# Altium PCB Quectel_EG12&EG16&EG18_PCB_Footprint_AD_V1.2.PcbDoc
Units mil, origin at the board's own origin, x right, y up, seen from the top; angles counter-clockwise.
Board outline 6000 x 4000 mil, 2 copper layers (Top Layer, Bottom Layer); 1 components, 0 nets, 299 pads, 0 vias.
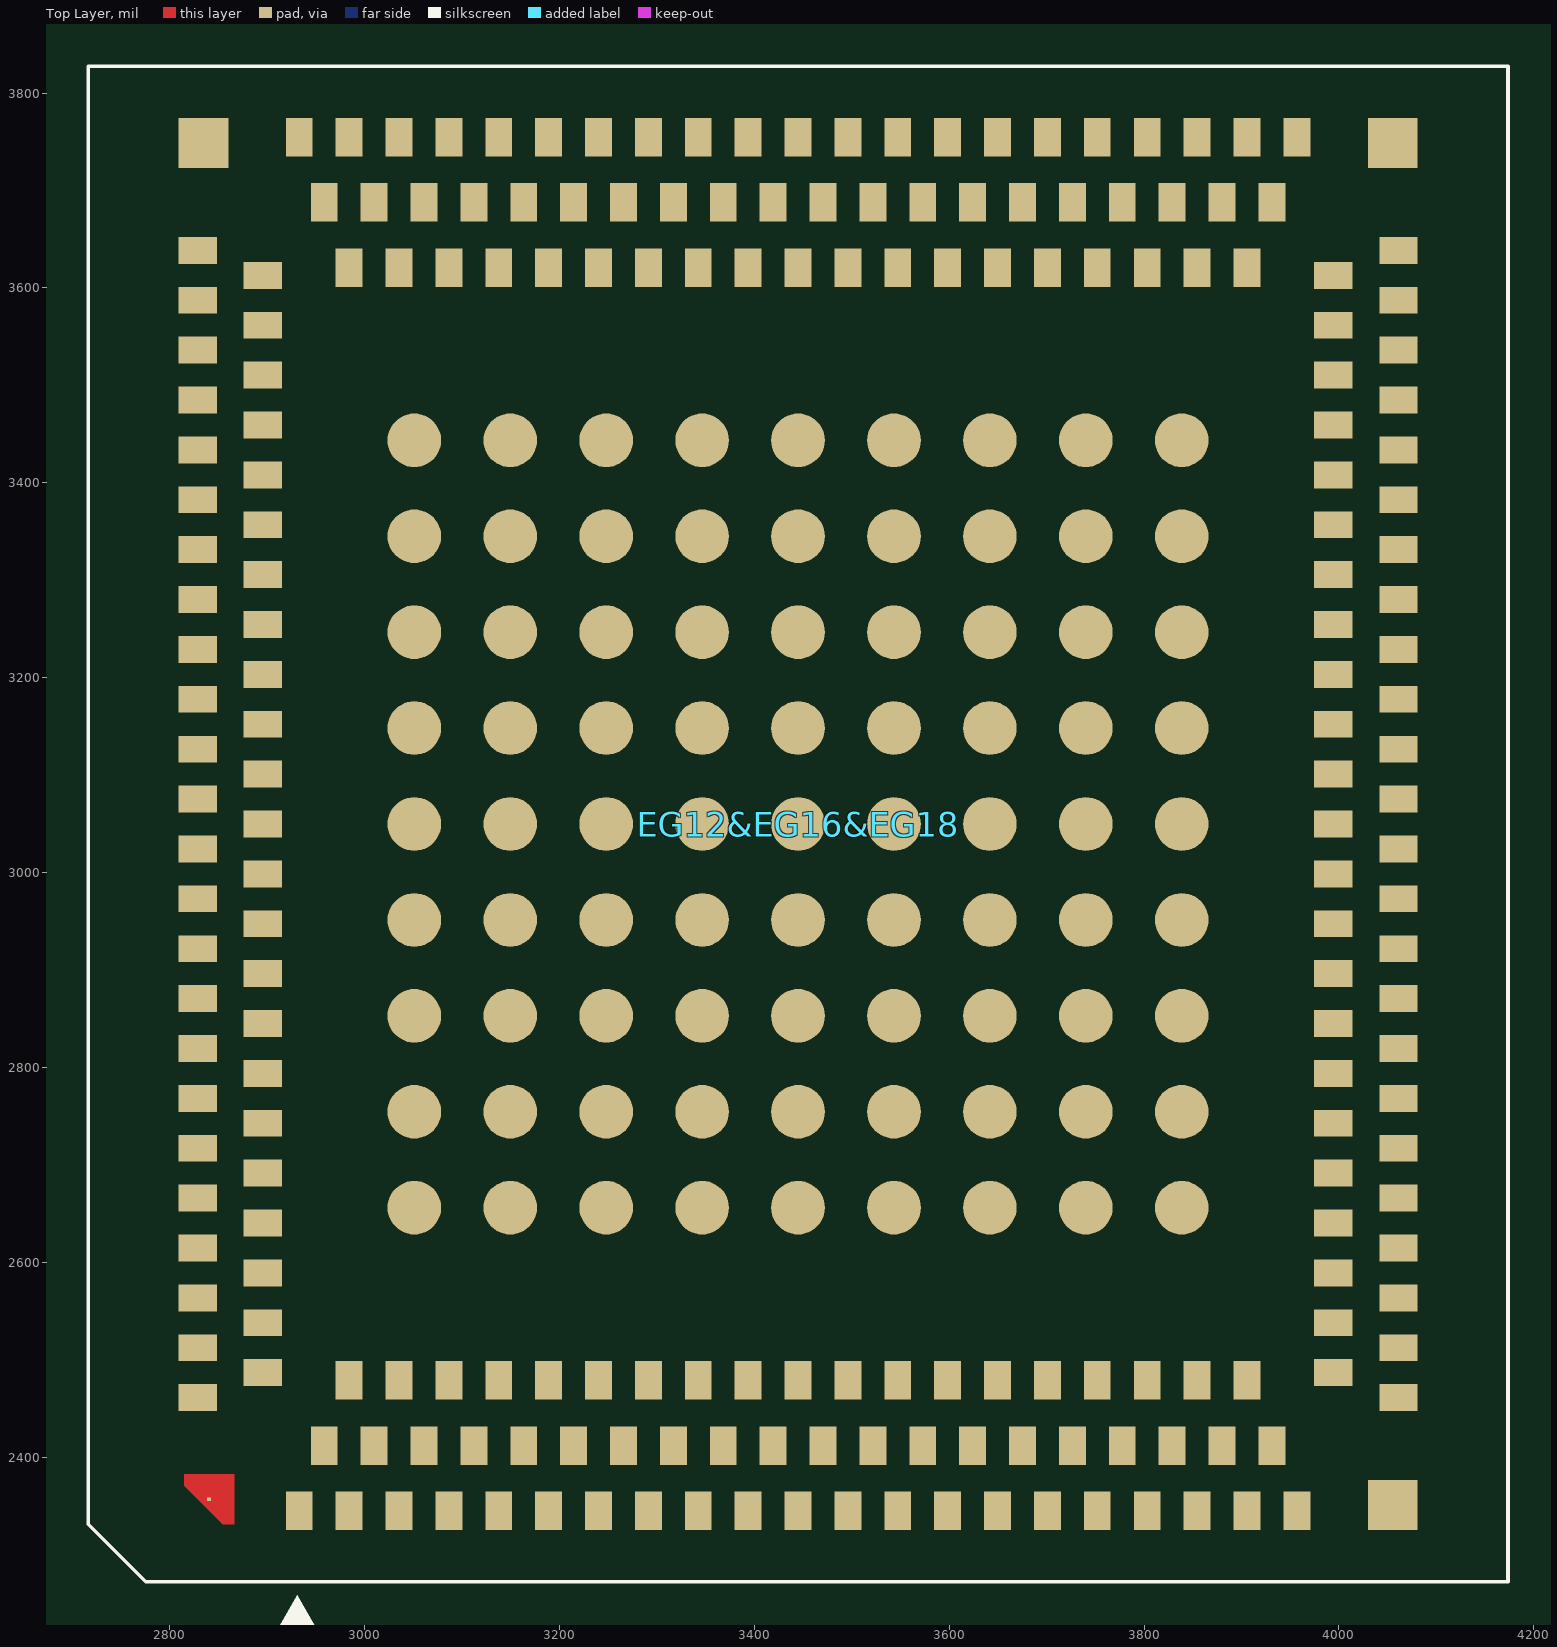
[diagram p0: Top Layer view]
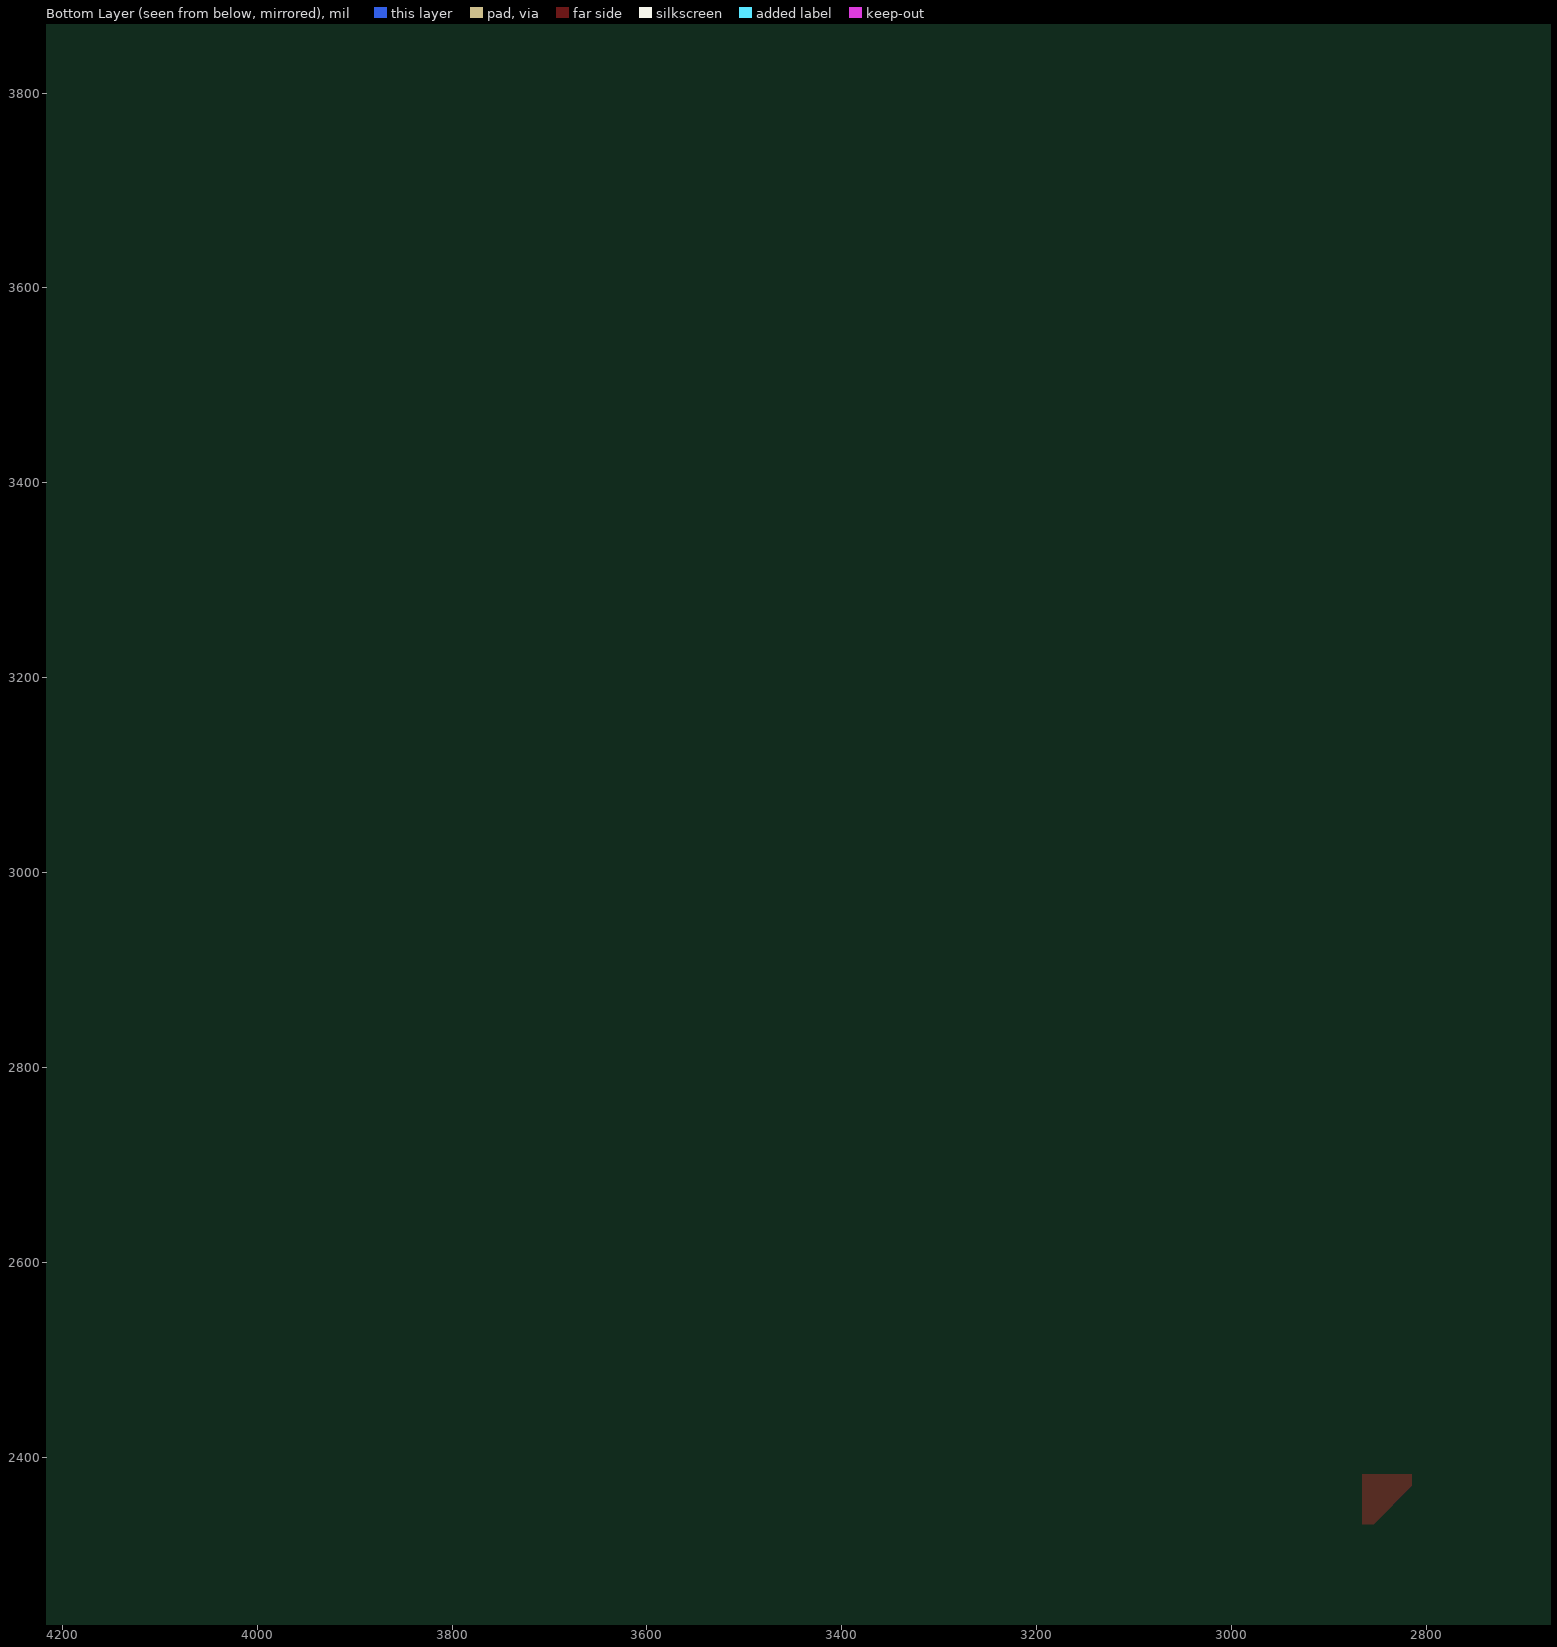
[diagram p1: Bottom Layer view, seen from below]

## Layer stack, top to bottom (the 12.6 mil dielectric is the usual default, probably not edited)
Top Layer: signal copper 1.4
Dielectric: dielectric 12.6, FR-4, Dk 4.8
Bottom Layer: signal copper 1.4

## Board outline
1000,1000 7000,1000 7000,5000 1000,5000

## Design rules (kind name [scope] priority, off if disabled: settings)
Clearance [All] p1: gap=10
PolygonConnect [All] p1: connectstyle=Relief reliefconductorwidth=10 reliefentries=4 polygonreliefangle="90 Angle" airgapwidth=10
RoutingVias [All] p1: holewidth=28 width=50 viastyle="Through Hole" minholewidth=28 minwidth=50 maxholewidth=28 maxwidth=50
SolderMaskExpansion [All] p1: expansion=4
Width [All] p1: maxlimit=10 minlimit=10 preferedwidth=10
28 further rules are at their usual default settings.

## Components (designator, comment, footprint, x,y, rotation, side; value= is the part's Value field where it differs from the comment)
EG12&EG16&EG18 "Comment" EG12&EG16&EG18 3445,3050 r0 top

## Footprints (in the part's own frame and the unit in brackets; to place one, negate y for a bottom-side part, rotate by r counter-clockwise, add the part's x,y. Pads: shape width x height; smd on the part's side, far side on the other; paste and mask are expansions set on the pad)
EG12&EG16&EG18 [mm]
  rect 0.7x1 smd mask+0.05: 1(-13,-17.9) 2(-12.35,-16.2) 3(-11.7,-17.9) 4(-11.05,-16.2) 5(-10.4,-17.9) 6(-9.75,-16.2) 7(-9.1,-17.9) 8(-8.45,-16.2) 9(-7.8,-17.9) 10(-7.15,-16.2) 11(-6.5,-17.9) 12(-5.85,-16.2) 13(-5.2,-17.9) 14(-4.55,-16.2) 15(-3.9,-17.9) 16(-3.25,-16.2) 17(-2.6,-17.9) 18(-1.95,-16.2) 19(-1.3,-17.9) 20(-0.65,-16.2) 21(0,-17.9) 22(0.65,-16.2) 23(1.3,-17.9) 24(1.95,-16.2) 25(2.6,-17.9) 26(3.25,-16.2) 27(3.9,-17.9) 28(4.55,-16.2) 29(5.2,-17.9) 30(5.85,-16.2) 31(6.5,-17.9) 32(7.15,-16.2) 33(7.8,-17.9) 34(8.45,-16.2) 35(9.1,-17.9) 36(9.75,-16.2) 37(10.4,-17.9) 38(11.05,-16.2) 39(11.7,-17.9) 40(12.35,-16.2) 41(13,-17.9) 89(13,17.9) 90(12.35,16.2) 91(11.7,17.9) 92(11.05,16.2) 93(10.4,17.9) 94(9.75,16.2) 95(9.1,17.9) 96(8.45,16.2) 97(7.8,17.9) 98(7.15,16.2) 99(6.5,17.9) 100(5.85,16.2) 101(5.2,17.9) 102(4.55,16.2) 103(3.9,17.9) 104(3.25,16.2) 105(2.6,17.9) 106(1.95,16.2) 107(1.3,17.9) 108(0.65,16.2) 109(0,17.9) 110(-0.65,16.2) 111(-1.3,17.9) 112(-1.95,16.2) 113(-2.6,17.9) 114(-3.25,16.2) 115(-3.9,17.9) 116(-4.55,16.2) 117(-5.2,17.9) 118(-5.85,16.2) 119(-6.5,17.9) 120(-7.15,16.2) 121(-7.8,17.9) 122(-8.45,16.2) 123(-9.1,17.9) 124(-9.75,16.2) 125(-10.4,17.9) 126(-11.05,16.2) 127(-11.7,17.9) 128(-12.35,16.2) 129(-13,17.9) 177(-11.7,-14.5) 178(-10.4,-14.5) 179(-9.1,-14.5) 180(-7.8,-14.5) 181(-6.5,-14.5) 182(-5.2,-14.5) 183(-3.9,-14.5) 184(-2.6,-14.5) 185(-1.3,-14.5) 186(0,-14.5) 187(1.3,-14.5) 188(2.6,-14.5) 189(3.9,-14.5) 190(5.2,-14.5) 191(6.5,-14.5) 192(7.8,-14.5) 193(9.1,-14.5) 194(10.4,-14.5) 195(11.7,-14.5) 196(11.7,14.5) 197(10.4,14.5) 198(9.1,14.5) 199(7.8,14.5) 200(6.5,14.5) 201(5.2,14.5) 202(3.9,14.5) 203(2.6,14.5) 204(1.3,14.5) 205(0,14.5) 206(-1.3,14.5) 207(-2.6,14.5) 208(-3.9,14.5) 209(-5.2,14.5) 210(-6.5,14.5) 211(-7.8,14.5) 212(-9.1,14.5) 213(-10.4,14.5) 214(-11.7,14.5)
  rect 1x0.7 smd mask+0.05: 42(15.65,-14.95) 43(13.95,-14.3) 44(15.65,-13.65) 45(13.95,-13) 46(15.65,-12.35) 47(13.95,-11.7) 48(15.65,-11.05) 49(13.95,-10.4) 50(15.65,-9.75) 51(13.95,-9.1) 52(15.65,-8.45) 53(13.95,-7.8) 54(15.65,-7.15) 55(13.95,-6.5) 56(15.65,-5.85) 57(13.95,-5.2) 58(15.65,-4.55) 59(13.95,-3.9) 60(15.65,-3.25) 61(13.95,-2.6) 62(15.65,-1.95) 63(13.95,-1.3) 64(15.65,-0.65) 65(13.95,0) 66(15.65,0.65) 67(13.95,1.3) 68(15.65,1.95) 69(13.95,2.6) 70(15.65,3.25) 71(13.95,3.9) 72(15.65,4.55) 73(13.95,5.2) 74(15.65,5.85) 75(13.95,6.5) 76(15.65,7.15) 77(13.95,7.8) 78(15.65,8.45) 79(13.95,9.1) 80(15.65,9.75) 81(13.95,10.4) 82(15.65,11.05) 83(13.95,11.7) 84(15.65,12.35) 85(13.95,13) 86(15.65,13.65) 87(13.95,14.3) 88(15.65,14.95) 130(-15.65,14.95) 131(-13.95,14.3) 132(-15.65,13.65) 133(-13.95,13) 134(-15.65,12.35) 135(-13.95,11.7) 136(-15.65,11.05) 137(-13.95,10.4) 138(-15.65,9.75) 139(-13.95,9.1) 140(-15.65,8.45) 141(-13.95,7.8) 142(-15.65,7.15) 143(-13.95,6.5) 144(-15.65,5.85) 145(-13.95,5.2) 146(-15.65,4.55) 147(-13.95,3.9) 148(-15.65,3.25) 149(-13.95,2.6) 150(-15.65,1.95) 151(-13.95,1.3) 152(-15.65,0.65) 153(-13.95,0) 154(-15.65,-0.65) 155(-13.95,-1.3) 156(-15.65,-1.95) 157(-13.95,-2.6) 158(-15.65,-3.25) 159(-13.95,-3.9) 160(-15.65,-4.55) 161(-13.95,-5.2) 162(-15.65,-5.85) 163(-13.95,-6.5) 164(-15.65,-7.15) 165(-13.95,-7.8) 166(-15.65,-8.45) 167(-13.95,-9.1) 168(-15.65,-9.75) 169(-13.95,-10.4) 170(-15.65,-11.05) 171(-13.95,-11.7) 172(-15.65,-12.35) 173(-13.95,-13) 174(-15.65,-13.65) 175(-13.95,-14.3) 176(-15.65,-14.95)
  round 1.4 smd mask+0.05: 215(-10,10) 216(-7.5,10) 217(-5,10) 218(-2.5,10) 219(0,10) 220(2.5,10) 221(5,10) 222(7.5,10) 223(10,10) 224(-10,7.5) 225(-7.5,7.5) 226(-5,7.5) 227(-2.5,7.5) 228(0,7.5) 229(2.5,7.5) 230(5,7.5) 231(7.5,7.5) 232(10,7.5) 233(-10,5) 234(-7.5,5) 235(-5,5) 236(-2.5,5) 237(0,5) 238(2.5,5) 239(5,5) 240(7.5,5) 241(10,5) 242(-10,2.5) 243(-7.5,2.5) 244(-5,2.5) 245(-2.5,2.5) 246(0,2.5) 247(2.5,2.5) 248(5,2.5) 249(7.5,2.5) 250(10,2.5) 251(-10,0) 252(-7.5,0) 253(-5,0) 254(-2.5,0) 255(0,0) 256(2.5,0) 257(5,0) 258(7.5,0) 259(10,0) 260(-10,-2.5) 261(-7.5,-2.5) 262(-5,-2.5) 263(-2.5,-2.5) 264(0,-2.5) 265(2.5,-2.5) 266(5,-2.5) 267(7.5,-2.5) 268(10,-2.5) 269(-10,-5) 270(-7.5,-5) 271(-5,-5) 272(-2.5,-5) 273(0,-5) 274(2.5,-5) 275(5,-5) 276(7.5,-5) 277(10,-5) 278(-10,-7.5) 279(-7.5,-7.5) 280(-5,-7.5) 281(-2.5,-7.5) 282(0,-7.5) 283(2.5,-7.5) 284(5,-7.5) 285(7.5,-7.5) 286(10,-7.5) 287(-10,-10) 288(-7.5,-10) 289(-5,-10) 290(-2.5,-10) 291(0,-10) 292(2.5,-10) 293(5,-10) 294(7.5,-10) 295(10,-10)
  rect 0.1x0.1 smd mask+0.05: 296(-15.35,-17.6)
  rect 1.3x1.3 smd mask+0.05: 297(15.5,-17.75) 298(15.5,17.75) 299(-15.5,17.75)
  Top Layer region: -16,-16.95 -14.7,-16.95 -14.7,-18.25 -15,-18.25 -16,-17.25 -16,-16.95
  silkscreen extent -18.5,-21.2 18.5,19.75

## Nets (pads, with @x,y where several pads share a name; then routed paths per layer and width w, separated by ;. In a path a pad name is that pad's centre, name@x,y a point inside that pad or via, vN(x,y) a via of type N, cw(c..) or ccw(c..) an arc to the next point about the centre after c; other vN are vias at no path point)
pads on no net: EG12&EG16&EG18.1 EG12&EG16&EG18.2 EG12&EG16&EG18.3 EG12&EG16&EG18.4 EG12&EG16&EG18.5 EG12&EG16&EG18.6 EG12&EG16&EG18.7 EG12&EG16&EG18.8 EG12&EG16&EG18.9 EG12&EG16&EG18.10 EG12&EG16&EG18.11 EG12&EG16&EG18.12 EG12&EG16&EG18.13 EG12&EG16&EG18.14 EG12&EG16&EG18.15 EG12&EG16&EG18.16 EG12&EG16&EG18.17 EG12&EG16&EG18.18 EG12&EG16&EG18.19 EG12&EG16&EG18.20 EG12&EG16&EG18.21 EG12&EG16&EG18.22 EG12&EG16&EG18.23 EG12&EG16&EG18.24 EG12&EG16&EG18.25 EG12&EG16&EG18.26 EG12&EG16&EG18.27 EG12&EG16&EG18.28 EG12&EG16&EG18.29 EG12&EG16&EG18.30 EG12&EG16&EG18.31 EG12&EG16&EG18.32 EG12&EG16&EG18.33 EG12&EG16&EG18.34 EG12&EG16&EG18.35 EG12&EG16&EG18.36 EG12&EG16&EG18.37 EG12&EG16&EG18.38 EG12&EG16&EG18.39 EG12&EG16&EG18.40 EG12&EG16&EG18.41 EG12&EG16&EG18.42 EG12&EG16&EG18.43 EG12&EG16&EG18.44 EG12&EG16&EG18.45 EG12&EG16&EG18.46 EG12&EG16&EG18.47 EG12&EG16&EG18.48 EG12&EG16&EG18.49 EG12&EG16&EG18.50 EG12&EG16&EG18.51 EG12&EG16&EG18.52 EG12&EG16&EG18.53 EG12&EG16&EG18.54 EG12&EG16&EG18.55 EG12&EG16&EG18.56 EG12&EG16&EG18.57 EG12&EG16&EG18.58 EG12&EG16&EG18.59 EG12&EG16&EG18.60 EG12&EG16&EG18.61 EG12&EG16&EG18.62 EG12&EG16&EG18.63 EG12&EG16&EG18.64 EG12&EG16&EG18.65 EG12&EG16&EG18.66 EG12&EG16&EG18.67 EG12&EG16&EG18.68 EG12&EG16&EG18.69 EG12&EG16&EG18.70 EG12&EG16&EG18.71 EG12&EG16&EG18.72 EG12&EG16&EG18.73 EG12&EG16&EG18.74 EG12&EG16&EG18.75 EG12&EG16&EG18.76 EG12&EG16&EG18.77 EG12&EG16&EG18.78 EG12&EG16&EG18.79 EG12&EG16&EG18.80 EG12&EG16&EG18.81 EG12&EG16&EG18.82 EG12&EG16&EG18.83 EG12&EG16&EG18.84 EG12&EG16&EG18.85 EG12&EG16&EG18.86 EG12&EG16&EG18.87 EG12&EG16&EG18.88 EG12&EG16&EG18.89 EG12&EG16&EG18.90 EG12&EG16&EG18.91 EG12&EG16&EG18.92 EG12&EG16&EG18.93 EG12&EG16&EG18.94 EG12&EG16&EG18.95 EG12&EG16&EG18.96 EG12&EG16&EG18.97 EG12&EG16&EG18.98 EG12&EG16&EG18.99 EG12&EG16&EG18.100 EG12&EG16&EG18.101 EG12&EG16&EG18.102 EG12&EG16&EG18.103 EG12&EG16&EG18.104 EG12&EG16&EG18.105 EG12&EG16&EG18.106 EG12&EG16&EG18.107 EG12&EG16&EG18.108 EG12&EG16&EG18.109 EG12&EG16&EG18.110 EG12&EG16&EG18.111 EG12&EG16&EG18.112 EG12&EG16&EG18.113 EG12&EG16&EG18.114 EG12&EG16&EG18.115 EG12&EG16&EG18.116 EG12&EG16&EG18.117 EG12&EG16&EG18.118 EG12&EG16&EG18.119 EG12&EG16&EG18.120 EG12&EG16&EG18.121 EG12&EG16&EG18.122 EG12&EG16&EG18.123 EG12&EG16&EG18.124 EG12&EG16&EG18.125 EG12&EG16&EG18.126 EG12&EG16&EG18.127 EG12&EG16&EG18.128 EG12&EG16&EG18.129 EG12&EG16&EG18.130 EG12&EG16&EG18.131 EG12&EG16&EG18.132 EG12&EG16&EG18.133 EG12&EG16&EG18.134 EG12&EG16&EG18.135 EG12&EG16&EG18.136 EG12&EG16&EG18.137 EG12&EG16&EG18.138 EG12&EG16&EG18.139 EG12&EG16&EG18.140 EG12&EG16&EG18.141 EG12&EG16&EG18.142 EG12&EG16&EG18.143 EG12&EG16&EG18.144 EG12&EG16&EG18.145 EG12&EG16&EG18.146 EG12&EG16&EG18.147 EG12&EG16&EG18.148 EG12&EG16&EG18.149 EG12&EG16&EG18.150 EG12&EG16&EG18.151 EG12&EG16&EG18.152 EG12&EG16&EG18.153 EG12&EG16&EG18.154 EG12&EG16&EG18.155 EG12&EG16&EG18.156 EG12&EG16&EG18.157 EG12&EG16&EG18.158 EG12&EG16&EG18.159 EG12&EG16&EG18.160 EG12&EG16&EG18.161 EG12&EG16&EG18.162 EG12&EG16&EG18.163 EG12&EG16&EG18.164 EG12&EG16&EG18.165 EG12&EG16&EG18.166 EG12&EG16&EG18.167 EG12&EG16&EG18.168 EG12&EG16&EG18.169 EG12&EG16&EG18.170 EG12&EG16&EG18.171 EG12&EG16&EG18.172 EG12&EG16&EG18.173 EG12&EG16&EG18.174 EG12&EG16&EG18.175 EG12&EG16&EG18.176 EG12&EG16&EG18.177 EG12&EG16&EG18.178 EG12&EG16&EG18.179 EG12&EG16&EG18.180 EG12&EG16&EG18.181 EG12&EG16&EG18.182 EG12&EG16&EG18.183 EG12&EG16&EG18.184 EG12&EG16&EG18.185 EG12&EG16&EG18.186 EG12&EG16&EG18.187 EG12&EG16&EG18.188 EG12&EG16&EG18.189 EG12&EG16&EG18.190 EG12&EG16&EG18.191 EG12&EG16&EG18.192 EG12&EG16&EG18.193 EG12&EG16&EG18.194 EG12&EG16&EG18.195 EG12&EG16&EG18.196 EG12&EG16&EG18.197 EG12&EG16&EG18.198 EG12&EG16&EG18.199 EG12&EG16&EG18.200 EG12&EG16&EG18.201 EG12&EG16&EG18.202 EG12&EG16&EG18.203 EG12&EG16&EG18.204 EG12&EG16&EG18.205 EG12&EG16&EG18.206 EG12&EG16&EG18.207 EG12&EG16&EG18.208 EG12&EG16&EG18.209 EG12&EG16&EG18.210 EG12&EG16&EG18.211 EG12&EG16&EG18.212 EG12&EG16&EG18.213 EG12&EG16&EG18.214 EG12&EG16&EG18.215 EG12&EG16&EG18.216 EG12&EG16&EG18.217 EG12&EG16&EG18.218 EG12&EG16&EG18.219 EG12&EG16&EG18.220 EG12&EG16&EG18.221 EG12&EG16&EG18.222 EG12&EG16&EG18.223 EG12&EG16&EG18.224 EG12&EG16&EG18.225 EG12&EG16&EG18.226 EG12&EG16&EG18.227 EG12&EG16&EG18.228 EG12&EG16&EG18.229 EG12&EG16&EG18.230 EG12&EG16&EG18.231 EG12&EG16&EG18.232 EG12&EG16&EG18.233 EG12&EG16&EG18.234 EG12&EG16&EG18.235 EG12&EG16&EG18.236 EG12&EG16&EG18.237 EG12&EG16&EG18.238 EG12&EG16&EG18.239 EG12&EG16&EG18.240 EG12&EG16&EG18.241 EG12&EG16&EG18.242 EG12&EG16&EG18.243 EG12&EG16&EG18.244 EG12&EG16&EG18.245 EG12&EG16&EG18.246 EG12&EG16&EG18.247 EG12&EG16&EG18.248 EG12&EG16&EG18.249 EG12&EG16&EG18.250 EG12&EG16&EG18.251 EG12&EG16&EG18.252 EG12&EG16&EG18.253 EG12&EG16&EG18.254 EG12&EG16&EG18.255 EG12&EG16&EG18.256 EG12&EG16&EG18.257 EG12&EG16&EG18.258 EG12&EG16&EG18.259 EG12&EG16&EG18.260 EG12&EG16&EG18.261 EG12&EG16&EG18.262 EG12&EG16&EG18.263 EG12&EG16&EG18.264 EG12&EG16&EG18.265 EG12&EG16&EG18.266 EG12&EG16&EG18.267 EG12&EG16&EG18.268 EG12&EG16&EG18.269 EG12&EG16&EG18.270 EG12&EG16&EG18.271 EG12&EG16&EG18.272 EG12&EG16&EG18.273 EG12&EG16&EG18.274 EG12&EG16&EG18.275 EG12&EG16&EG18.276 EG12&EG16&EG18.277 EG12&EG16&EG18.278 EG12&EG16&EG18.279 EG12&EG16&EG18.280 EG12&EG16&EG18.281 EG12&EG16&EG18.282 EG12&EG16&EG18.283 EG12&EG16&EG18.284 EG12&EG16&EG18.285 EG12&EG16&EG18.286 EG12&EG16&EG18.287 EG12&EG16&EG18.288 EG12&EG16&EG18.289 EG12&EG16&EG18.290 EG12&EG16&EG18.291 EG12&EG16&EG18.292 EG12&EG16&EG18.293 EG12&EG16&EG18.294 EG12&EG16&EG18.295 EG12&EG16&EG18.296 EG12&EG16&EG18.297 EG12&EG16&EG18.298 EG12&EG16&EG18.299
